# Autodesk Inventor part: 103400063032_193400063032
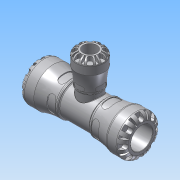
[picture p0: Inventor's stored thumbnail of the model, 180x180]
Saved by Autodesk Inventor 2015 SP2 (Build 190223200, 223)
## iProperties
Created: 2016-12
Part Number: 103400063032_193400063032
Material: PVC-Piping
Description: PLASSON REDUCING TEE 63X32X63 SERIES 1
Document SubType Name: Modeling
Designer: KIM
Mass: 664.223 g
Surface Area: 733.008 cm^2
Volume: 474.445 cm^3
Density: 1.4 g/cm^3
Appearance: Smooth - White
Author: KIM
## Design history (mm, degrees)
derived "1034.ipt"
feature "Solid1::1034.ipt"
tag "TaggingFeature1"
body "Solid1"
other parameters: "d9" = 12.125, "d11" = 103, "d12" = 78.75, "d230" = 58, "d232" = 9, "d1" = 37.8, "d2" = 63, "d3" = 78.75, "d4" = 103, "d8" = 87.55, "d13" = 9.7, "d14" = 9.7, "d15" = 0, "d17" = 360 deg, "d19" = 8 deg, "d20" = 1.26, "d21" = 1.26, "d22" = 8 deg, "d24" = 0, "d26" = 360 deg, "d33" = 10.3, "d43" = 80.34, "d51" = 1.03, "d54" = 22.05, "d55" = 13.86, "d57" = 19.012, "d58" = 0, "d74" = 0, "d77" = 5.25, "d79" = 80.34, "d80" = 262, "d82" = 1.26, "d115" = 360 deg, "d139" = 9.7, "d140" = 0, "d142" = 360 deg, "d207" = 90 deg, "d209" = 22.68, "d210" = 32, "d212" = 58, "d213" = 49.3, "d215" = 45.24, "d216" = 2.66667, "d217" = 54, "d226" = 54, "d228" = 18.7425, "d229" = 7.2, "d233" = 7.2, "d234" = 0, "d236" = 360 deg, "d238" = 8 deg, "d239" = 8 deg, "d240" = 1.26, "d241" = 1.26, "d243" = 0, "d245" = 360 deg, "d247" = 2.06, "d248" = 5.4, "d249" = 3.24, "d250" = 9.52, "d252" = 11.2, "d253" = 7.36, "d254" = 19.012, "d255" = 0, "d257" = 360 deg, "d259" = 1.26, "d261" = 0, "d262" = 2.06, "d264" = 0, "d266" = 0, "d267" = 1.03, "d_" = 63, "E_" = 103, "H_" = 262, "d_1" = 32, "E_1" = 58, "l_1" = 54
